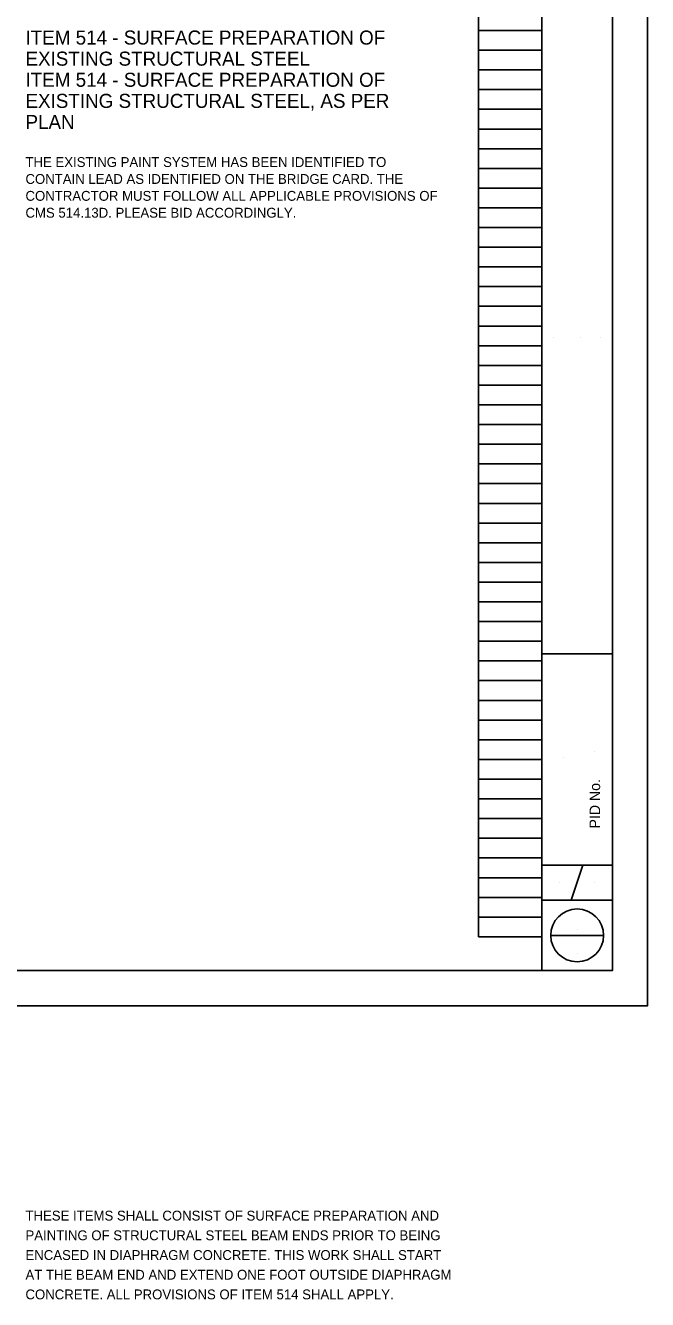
# Model space of a CAD drawing. Extents: x -51.6 to 45.5, y -38.3 to 35.3.
# Drawn here: x 25.16 to 34, y -4.18 to 13.93 of the extents above; entities that cross this region are included whole.
import ezdxf

# ---------------------------------------------------------------- set-up
doc = ezdxf.new("R2010")
doc.units = 0
for name, color, linetype in [('BD_P_Text', 7, 'Continuous'), ('SH_Border', 7, 'Continuous'), ('SH_Cut_Line', 7, 'Continuous'), ('SH_Data', 7, 'Continuous')]:
    doc.layers.add(name, color=color, linetype=linetype)

msp = doc.modelspace()

# ---------------------------------------------------------------- linework, layer by layer
at = {"layer": 'SH_Border'}
for p, q in [((32.5, 0.5), (32.5, 21.5)), ((32.5, 5), (33.5, 5)), ((32.5, 2), (33.5, 2)), ((32.917, 1.5), (33.083, 2)), ((32.5, 1.5), (33.5, 1.5))]:
    msp.add_line(p, q, dxfattribs=at)
msp.add_lwpolyline([(2, 21.5), (33.5, 21.5), (33.5, 0.5), (2, 0.5)], close=True, dxfattribs=at)
at = {"layer": 'SH_Cut_Line'}
msp.add_lwpolyline([(0, 22), (34, 22), (34, 0), (0, 0)], close=True, dxfattribs=at)
at = {"layer": 'SH_Data'}
for p, q in [((31.6, 0.98), (31.6, 21.14)), ((32.5, 0.98), (32.5, 21.14)), ((31.6, 13.86), (32.5, 13.86)), ((31.6, 13.58), (32.5, 13.58)), ((31.6, 13.3), (32.5, 13.3)), ((31.6, 13.02), (32.5, 13.02)), ((31.6, 12.74), (32.5, 12.74)), ((31.6, 12.46), (32.5, 12.46)), ((31.6, 12.18), (32.5, 12.18)), ((31.6, 11.9), (32.5, 11.9)), ((31.6, 11.62), (32.5, 11.62)), ((31.6, 11.34), (32.5, 11.34)), ((31.6, 11.06), (32.5, 11.06)), ((31.6, 10.78), (32.5, 10.78)), ((31.6, 10.5), (32.5, 10.5)), ((31.6, 10.22), (32.5, 10.22)), ((31.6, 9.94), (32.5, 9.94)), ((31.6, 9.66), (32.5, 9.66)), ((32.667, 9.5), (32.667, 9.5)), ((33.042, 9.5), (33.042, 9.5)), ((33.333, 9.5), (33.333, 9.5)), ((31.6, 9.38), (32.5, 9.38)), ((31.6, 9.1), (32.5, 9.1)), ((31.6, 8.82), (32.5, 8.82)), ((31.6, 8.54), (32.5, 8.54)), ((31.6, 8.26), (32.5, 8.26)), ((31.6, 7.98), (32.5, 7.98)), ((31.6, 7.7), (32.5, 7.7)), ((31.6, 7.42), (32.5, 7.42)), ((31.6, 7.14), (32.5, 7.14)), ((31.6, 6.86), (32.5, 6.86)), ((31.6, 6.58), (32.5, 6.58)), ((31.6, 6.3), (32.5, 6.3)), ((31.6, 6.02), (32.5, 6.02)), ((31.6, 5.74), (32.5, 5.74)), ((31.6, 5.46), (32.5, 5.46)), ((31.6, 5.18), (32.5, 5.18)), ((31.6, 4.9), (32.5, 4.9)), ((31.6, 4.62), (32.5, 4.62)), ((31.6, 4.34), (32.5, 4.34)), ((31.6, 4.06), (32.5, 4.06)), ((31.6, 3.78), (32.5, 3.78)), ((31.6, 3.5), (32.5, 3.5)), ((32.8, 3.53), (32.8, 3.53)), ((33.25, 3.618), (33.25, 3.618)), ((31.6, 3.22), (32.5, 3.22)), ((31.6, 2.94), (32.5, 2.94)), ((31.6, 2.66), (32.5, 2.66)), ((31.6, 2.38), (32.5, 2.38)), ((31.6, 2.1), (32.5, 2.1)), ((31.6, 1.82), (32.5, 1.82)), ((32.75, 1.75), (32.75, 1.75)), ((33.25, 1.75), (33.25, 1.75)), ((31.6, 1.54), (32.5, 1.54)), ((31.6, 1.26), (32.5, 1.26)), ((31.6, 0.98), (32.5, 0.98)), ((32.625, 1), (33.375, 1)), ((33, 1.085), (33, 1.085)), ((33, 0.745), (33, 0.745))]:
    msp.add_line(p, q, dxfattribs=at)
msp.add_circle((33, 1), 0.375, dxfattribs=at)

# ---------------------------------------------------------------- texts
at = {"layer": 'BD_P_Text'}
for s, height, p in [('ITEM 514 - SURFACE PREPARATION OF ', 0.2, (25.16, 13.66)), ('EXISTING STRUCTURAL STEEL', 0.2, (25.16, 13.36)), ('ITEM 514 - SURFACE PREPARATION OF ', 0.2, (25.16, 13.06)), ('EXISTING STRUCTURAL STEEL, AS PER ', 0.2, (25.16, 12.76)), ('PLAN', 0.2, (25.16, 12.46)), ('THE EXISTING PAINT SYSTEM HAS BEEN IDENTIFIED TO ', 0.14, (25.16, 11.92)), ('CONTAIN LEAD AS IDENTIFIED ON THE BRIDGE CARD. THE ', 0.14, (25.16, 11.68)), ('CONTRACTOR MUST FOLLOW ALL APPLICABLE PROVISIONS OF ', 0.14, (25.16, 11.44)), ('CMS 514.13D. PLEASE BID ACCORDINGLY.', 0.14, (25.16, 11.2)), ('THESE ITEMS SHALL CONSIST OF SURFACE PREPARATION AND ', 0.14, (25.16, -3.053)), ('PAINTING OF STRUCTURAL STEEL BEAM ENDS PRIOR TO BEING ', 0.14, (25.16, -3.333)), ('ENCASED IN DIAPHRAGM CONCRETE. THIS WORK SHALL START ', 0.14, (25.16, -3.613)), ('AT THE BEAM END AND EXTEND ONE FOOT OUTSIDE DIAPHRAGM ', 0.14, (25.16, -3.893)), ('CONCRETE. ALL PROVISIONS OF ITEM 514 SHALL APPLY.', 0.14, (25.16, -4.173))]:
    msp.add_text(s, height=height, dxfattribs=at).set_placement(p)
at = {"layer": 'SH_Data'}
msp.add_text('PID No.', height=0.15, rotation=90, dxfattribs=at).set_placement((33.327, 2.519))

doc.saveas('drawing.dxf')
